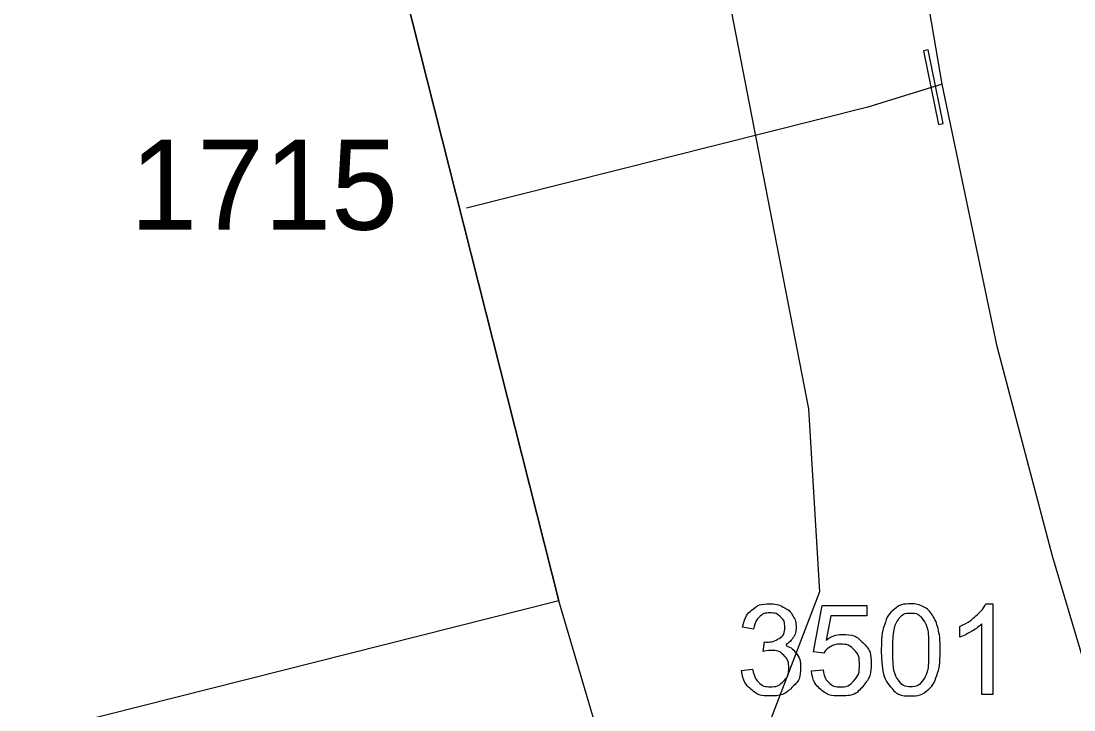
# Model space of a CAD drawing. Extents: x -562248 to -562040, y -1079385 to -1079027.
# Drawn here: x -562143.23 to -562125.69, y -1079135.74 to -1079124.27 of the extents above; entities that cross this region are included whole.
import ezdxf

# ---------------------------------------------------------------- set-up
doc = ezdxf.new("R2010")
doc.units = 0
for name, color, linetype in [('Armatura vodovodní', 7, 'Continuous'), ('Parcela-polygon', 7, 'Continuous'), ('Parcela-text', 7, 'Continuous'), ('Popis šachty', 7, 'Continuous'), ('Vodovodní přípojka', 7, 'Continuous'), ('Vodovodní řad', 7, 'Continuous')]:
    doc.layers.add(name, color=color, linetype=linetype)

msp = doc.modelspace()

# ---------------------------------------------------------------- linework, layer by layer
at = {"layer": 'Armatura vodovodní'}
msp.add_lwpolyline([(-562127.946, -1079125.987), (-562127.87, -1079125.971), (-562128.12, -1079124.747), (-562128.197, -1079124.762)], close=True, dxfattribs=at)
at = {"layer": 'Parcela-polygon'}
for points in [[(-562132.29, -1079100.17), (-562132.68, -1079103.22), (-562132.95, -1079106.27), (-562133.02, -1079110.27), (-562133.03, -1079111.66), (-562133.02, -1079112.82), (-562132.9, -1079114.53), (-562132.89, -1079114.59), (-562132.42, -1079118.65), (-562131.55, -1079123.32), (-562130.11, -1079130.72), (-562129.93, -1079133.77), (-562130.82, -1079136.09), (-562133.17, -1079137.64), (-562132.36, -1079140.38), (-562140.21, -1079144.16), (-562153.733, -1079146.647)], [(-562155.326, -1079142.122), (-562133.17, -1079137.64), (-562134.27, -1079133.92), (-562143.55, -1079136.26), (-562147.68, -1079119.88), (-562138.41, -1079117.54), (-562138.9, -1079114.26), (-562147.01, -1079109.93), (-562156.09, -1079106.68)]]:
    msp.add_lwpolyline(points, dxfattribs=at)
for points in [[(-562130.11, -1079130.72), (-562129.93, -1079133.77), (-562130.82, -1079136.09), (-562133.17, -1079137.64), (-562134.27, -1079133.92), (-562138.41, -1079117.54), (-562138.9, -1079114.26), (-562132.9, -1079114.53), (-562132.89, -1079114.59), (-562132.42, -1079118.65), (-562131.55, -1079123.32)], [(-562147.68, -1079119.88), (-562138.41, -1079117.54), (-562134.27, -1079133.92), (-562143.55, -1079136.26)]]:
    msp.add_lwpolyline(points, close=True, dxfattribs=at)
at = {"layer": 'Popis šachty'}
for points in [[(-562129.859, -1079134.788), (-562130.032, -1079134.766), (-562129.886, -1079133.995), (-562129.141, -1079133.995), (-562129.141, -1079134.171), (-562129.739, -1079134.171), (-562129.82, -1079134.574)], [(-562127.16, -1079133.97), (-562127.042, -1079133.97), (-562127.042, -1079135.476)], [(-562127.042, -1079135.476), (-562127.226, -1079135.476), (-562127.226, -1079134.302)], [(-562131.026, -1079134.392), (-562131.21, -1079134.359)], [(-562127.594, -1079134.524), (-562127.594, -1079134.346)], [(-562130.865, -1079134.764), (-562130.845, -1079134.603)], [(-562131.229, -1079135.078), (-562131.044, -1079135.054)], [(-562130.065, -1079135.082), (-562129.871, -1079135.066)]]:
    msp.add_lwpolyline(points, dxfattribs=at)
for points in [[(-562131.21, -1079134.359), (-562131.176, -1079134.173), (-562131.057, -1079134.072), (-562130.937, -1079133.97), (-562130.759, -1079133.97), (-562130.636, -1079133.97), (-562130.533, -1079134.022), (-562130.429, -1079134.075), (-562130.374, -1079134.166), (-562130.32, -1079134.257), (-562130.32, -1079134.359), (-562130.32, -1079134.456), (-562130.372, -1079134.536), (-562130.424, -1079134.615), (-562130.526, -1079134.662), (-562130.393, -1079134.693), (-562130.32, -1079134.79), (-562130.246, -1079134.886), (-562130.246, -1079135.031), (-562130.246, -1079135.228), (-562130.39, -1079135.364), (-562130.533, -1079135.501), (-562130.752, -1079135.501), (-562130.949, -1079135.501), (-562131.08, -1079135.383), (-562131.21, -1079135.265), (-562131.229, -1079135.078)], [(-562130.845, -1079134.603), (-562130.827, -1079134.605), (-562130.815, -1079134.605), (-562130.698, -1079134.605), (-562130.604, -1079134.544), (-562130.509, -1079134.483), (-562130.509, -1079134.355), (-562130.509, -1079134.254), (-562130.578, -1079134.187), (-562130.647, -1079134.121), (-562130.755, -1079134.121), (-562130.862, -1079134.121), (-562130.934, -1079134.189), (-562131.006, -1079134.256), (-562131.026, -1079134.392)], [(-562128.9, -1079134.736), (-562128.9, -1079134.47), (-562128.845, -1079134.308), (-562128.79, -1079134.145), (-562128.682, -1079134.058), (-562128.574, -1079133.97), (-562128.411, -1079133.97), (-562128.29, -1079133.97), (-562128.199, -1079134.018), (-562128.108, -1079134.067), (-562128.049, -1079134.159), (-562127.99, -1079134.25), (-562127.956, -1079134.381), (-562127.922, -1079134.513), (-562127.922, -1079134.736), (-562127.922, -1079135), (-562127.976, -1079135.162), (-562128.031, -1079135.324), (-562128.138, -1079135.413), (-562128.246, -1079135.501), (-562128.411, -1079135.501), (-562128.628, -1079135.501), (-562128.751, -1079135.346), (-562128.9, -1079135.158), (-562128.9, -1079134.736)], [(-562128.71, -1079134.736), (-562128.71, -1079135.106), (-562128.624, -1079135.228), (-562128.537, -1079135.35), (-562128.411, -1079135.35), (-562128.284, -1079135.35), (-562128.198, -1079135.227), (-562128.112, -1079135.105), (-562128.112, -1079134.736), (-562128.112, -1079134.365), (-562128.198, -1079134.244), (-562128.284, -1079134.122), (-562128.413, -1079134.122), (-562128.539, -1079134.122), (-562128.615, -1079134.229), (-562128.71, -1079134.366), (-562128.71, -1079134.736)], [(-562127.594, -1079134.346), (-562127.44, -1079134.274), (-562127.324, -1079134.17), (-562127.208, -1079134.067), (-562127.16, -1079133.97)], [(-562127.226, -1079134.302), (-562127.292, -1079134.366), (-562127.4, -1079134.429), (-562127.508, -1079134.493), (-562127.594, -1079134.524)], [(-562129.82, -1079134.574), (-562129.685, -1079134.48), (-562129.537, -1079134.48), (-562129.34, -1079134.48), (-562129.205, -1079134.616), (-562129.07, -1079134.752), (-562129.07, -1079134.966), (-562129.07, -1079135.17), (-562129.189, -1079135.318), (-562129.333, -1079135.501), (-562129.583, -1079135.501), (-562129.787, -1079135.501), (-562129.917, -1079135.386), (-562130.046, -1079135.272), (-562130.065, -1079135.082)], [(-562129.871, -1079135.066), (-562129.85, -1079135.208), (-562129.772, -1079135.279), (-562129.694, -1079135.35), (-562129.583, -1079135.35), (-562129.449, -1079135.35), (-562129.357, -1079135.249), (-562129.265, -1079135.149), (-562129.265, -1079134.983), (-562129.265, -1079134.825), (-562129.354, -1079134.733), (-562129.442, -1079134.642), (-562129.586, -1079134.642), (-562129.675, -1079134.642), (-562129.747, -1079134.683), (-562129.818, -1079134.724), (-562129.859, -1079134.788)], [(-562131.044, -1079135.054), (-562131.013, -1079135.21), (-562130.937, -1079135.28), (-562130.861, -1079135.349), (-562130.751, -1079135.349), (-562130.62, -1079135.349), (-562130.531, -1079135.259), (-562130.442, -1079135.169), (-562130.442, -1079135.036), (-562130.442, -1079134.909), (-562130.525, -1079134.826), (-562130.608, -1079134.744), (-562130.736, -1079134.744), (-562130.788, -1079134.744), (-562130.865, -1079134.764)]]:
    msp.add_open_spline(points, degree=3, dxfattribs=at)
at = {"layer": 'Vodovodní přípojka'}
msp.add_lwpolyline([(-562127.886, -1079125.317), (-562129.122, -1079125.701), (-562135.81, -1079127.38)], dxfattribs=at)
at = {"layer": 'Vodovodní řad'}
msp.add_lwpolyline([(-562104.508, -1079195.68), (-562105.675, -1079193.599), (-562106.045, -1079192.495), (-562108.292, -1079185.845), (-562110.54, -1079179.194), (-562111.609, -1079176.901), (-562113.474, -1079171.283), (-562115.559, -1079165.192), (-562118.308, -1079157.281), (-562119.874, -1079152.505), (-562123.128, -1079142.718), (-562124.818, -1079137.317), (-562126.048, -1079133.176), (-562126.972, -1079129.683), (-562127.886, -1079125.317), (-562128.484, -1079121.808), (-562129.183, -1079117.074), (-562129.389, -1079112.24), (-562129.474, -1079106.997), (-562129.319, -1079103.524), (-562128.819, -1079100.288), (-562128.175, -1079096.35), (-562128.115, -1079096.032)], dxfattribs=at)

# ---------------------------------------------------------------- texts
at = {"layer": 'Parcela-text'}
msp.add_text('1715', height=1.5, dxfattribs=at).set_placement((-562141.41, -1079127.74))

doc.saveas('drawing.dxf')
